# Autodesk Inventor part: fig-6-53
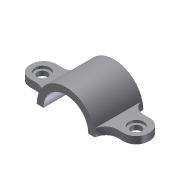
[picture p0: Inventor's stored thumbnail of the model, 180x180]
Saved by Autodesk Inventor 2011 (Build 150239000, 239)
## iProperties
Created: 2004-05
Part Number: fig-6-53
Document SubType Name: Modeling
Designer: CADCIM Technologies
Manufacturer: Standard
Standards Organization: Custom
Density: 1 g/cm^3
Author: CADCIM Technologies
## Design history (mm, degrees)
node "Sketch1"
sketch "Sketch2"
  geometry: L1 (23.378, 0)-(17.996, 0); L2 (-17.996, 0)-(-23.378, 0); A1 r 23.378 centre (0, 0) between (23.378, 0) and (-23.378, 0); A2 r 17.996 centre (0, 0) between (17.996, 0) and (-17.996, 0)
  constraints: 4 end point, 4 point on circle, 2 centre point, 1 collinear, 1 horizontal
extrude "Extrusion1" new body sketch "Sketch2" stored distance "d0" = 38.75; taper "d1" = 0 deg
sketch "Sketch3"
  geometry: L1 (23.378, 0)-(17.996, 0); L2 (-17.996, 0)-(-23.378, 0) reference; L3 (-23.378, 0)-(-47.662, 0); L4 (-47.662, 0)-(-47.662, 5.722); L5 (-47.662, 5.722)-(-22.667, 5.722); A1 r 17.996 centre (0, 0) between (17.996, 0) and (-17.996, 0) reference; A2 r 23.378 centre (0, 0) between (23.378, 0) and (-23.378, 0) reference; 1 further point
  constraints: 10 end point, 5 point on circle, 2 centre point, 1 collinear, 1 horizontal, 1 midpoint, 1 parallel, 1 perpendicular, 3 other
extrude "Extrusion2" join sketch "Sketch3" stored distance "d2" = 21; taper "d3" = 0 deg
fillet "Fillet1" dims "d4" = 10
hole "Hole1" diameter "d7" = 8; stored, may be unused: countersink angle "d11" = 90 deg, drill point angle "d13" = 118 deg; dims "d5" = 10, "d6" = 10, "d8" = 6, "d9" = 12, "d10" = 2, "d12" = 12
fillet "Fillet2" dims "d14" = 9.5
mirror "Mirror1"
body "Solid1"
